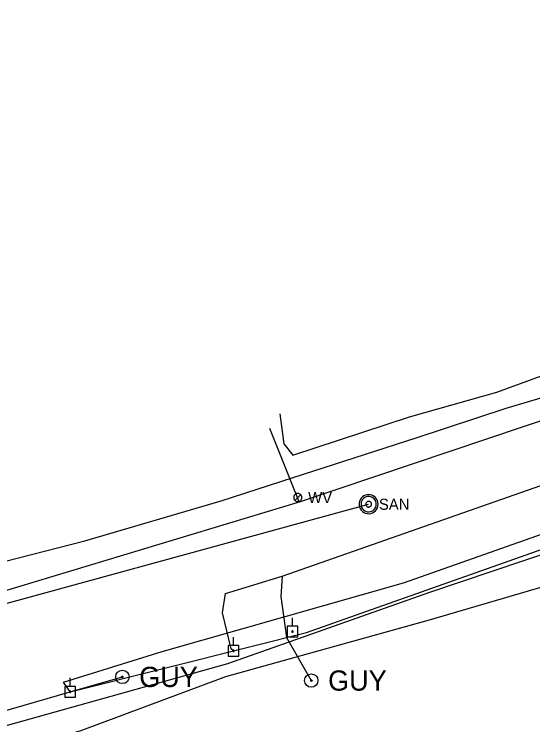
# Model space of a CAD drawing. Extents: x 596028 to 606371, y 330010 to 403088.
# Drawn here: x 604579.4 to 604758.9, y 333688.9 to 333935 of the extents above; entities that cross this region are included whole.
import ezdxf

# ---------------------------------------------------------------- set-up
doc = ezdxf.new("R2010")
doc.units = 0
for name, color, linetype in [('E_UTL_E_UG', 7, 'Continuous'), ('E_UTL_EGuyWire', 7, 'Continuous'), ('E_UTL_EPowerPole', 7, 'Continuous'), ('E_UTL_FO_UG_QWEST', 7, 'Continuous'), ('E_UTL_G_UG', 7, 'Continuous'), ('E_UTL_Overhead', 7, 'Continuous'), ('E_UTL_SAN_MH', 7, 'Continuous'), ('E_UTL_SAN_UG', 7, 'Continuous'), ('E_UTL_T_UG', 7, 'Continuous'), ('E_UTL_W', 7, 'Continuous'), ('E_UTL_W_UG', 7, 'Continuous')]:
    doc.layers.add(name, color=color, linetype=linetype)

msp = doc.modelspace()

# ---------------------------------------------------------------- linework, layer by layer
at = {"layer": 'E_UTL_E_UG'}
msp.add_line((604671.71, 333733.36), (604673.7, 333719.09), dxfattribs=at)
for points in [[(604440.14, 333718.83), (604480.42, 333725.03), (604538.85, 333736.02), (604603.87, 333752.62), (604651.09, 333766.43), (604675.97, 333774.58), (604718.55, 333788.33), (604749.73, 333798.5), (604768.73, 333804.21), (604803.48, 333815.07), (604806.49, 333819.63), (604807.09, 333825.4), (604807.44, 333834.72)], [(604598.8, 333700.36), (604596.5, 333703.7), (604630.64, 333714.29), (604714.18, 333738.06), (604794.04, 333766.23), (604819.54, 333774.15), (604828.3, 333774.47), (604835.57, 333767), (604842.31, 333740.21), (604846.52, 333720.82)], [(604655.31, 333714.51), (604654.49, 333715.25), (604651.55, 333727.64), (604652.56, 333734.31), (604672.23, 333740.35), (604765.98, 333773.32)], [(604672.23, 333740.35), (604671.71, 333733.36)]]:
    msp.add_lwpolyline(points, dxfattribs=at)
at = {"layer": 'E_UTL_EGuyWire'}
for p, q in [((604673.7, 333719.09), (604682.25, 333704.22)), ((604598.8, 333700.36), (604616.86, 333705.48))]:
    msp.add_line(p, q, dxfattribs=at)
for centre, radius in [((604616.86, 333705.48), 2.33), ((604682.25, 333704.22), 2.33), ((604616.86, 333705.48), 0.292), ((604682.25, 333704.22), 0.292)]:
    msp.add_circle(centre, radius, dxfattribs=at)
at = {"layer": 'E_UTL_EPowerPole'}
for points in [[(604675.7, 333723.02), (604675.7, 333725.93)], [(604677.55, 333723.02), (604673.86, 333723.02)], [(604673.86, 333723.02), (604673.86, 333719.33)], [(604675.97, 333721.18), (604675.97, 333721.22), (604675.96, 333721.27), (604675.94, 333721.31), (604675.91, 333721.34), (604675.87, 333721.37), (604675.83, 333721.39), (604675.79, 333721.41), (604675.75, 333721.42), (604675.7, 333721.41), (604675.66, 333721.4), (604675.62, 333721.38), (604675.58, 333721.36), (604675.55, 333721.32), (604675.52, 333721.29), (604675.51, 333721.24), (604675.5, 333721.2), (604675.5, 333721.15), (604675.51, 333721.11), (604675.52, 333721.07), (604675.55, 333721.03), (604675.58, 333721), (604675.62, 333720.97), (604675.66, 333720.95), (604675.7, 333720.94), (604675.75, 333720.94), (604675.79, 333720.95), (604675.83, 333720.96), (604675.87, 333720.98), (604675.91, 333721.01), (604675.94, 333721.05), (604675.96, 333721.09), (604675.97, 333721.13), (604675.97, 333721.18)], [(604677.55, 333719.33), (604677.55, 333723.02)], [(604655.28, 333716.36), (604655.28, 333719.26)], [(604673.86, 333719.33), (604677.55, 333719.33)], [(604657.13, 333716.36), (604653.44, 333716.36)], [(604653.44, 333716.36), (604653.44, 333712.66)], [(604657.13, 333712.66), (604657.13, 333716.36)], [(604655.55, 333714.51), (604655.55, 333714.56), (604655.54, 333714.6), (604655.51, 333714.64), (604655.49, 333714.68), (604655.45, 333714.71), (604655.41, 333714.73), (604655.37, 333714.74), (604655.33, 333714.75), (604655.28, 333714.75), (604655.24, 333714.74), (604655.19, 333714.72), (604655.16, 333714.69), (604655.13, 333714.66), (604655.1, 333714.62), (604655.09, 333714.58), (604655.08, 333714.54), (604655.08, 333714.49), (604655.09, 333714.45), (604655.1, 333714.4), (604655.13, 333714.37), (604655.16, 333714.33), (604655.19, 333714.31), (604655.24, 333714.29), (604655.28, 333714.28), (604655.33, 333714.27), (604655.37, 333714.28), (604655.41, 333714.3), (604655.45, 333714.32), (604655.49, 333714.35), (604655.51, 333714.38), (604655.54, 333714.42), (604655.55, 333714.47), (604655.55, 333714.51)], [(604653.44, 333712.66), (604657.13, 333712.66)], [(604598.77, 333702.21), (604598.77, 333705.12)], [(604600.61, 333702.21), (604596.92, 333702.21)], [(604596.92, 333702.21), (604596.92, 333698.52)], [(604600.61, 333698.52), (604600.61, 333702.21)], [(604599.04, 333700.36), (604599.03, 333700.41), (604599.02, 333700.45), (604599, 333700.49), (604598.97, 333700.53), (604598.94, 333700.56), (604598.9, 333700.58), (604598.86, 333700.6), (604598.81, 333700.6), (604598.77, 333700.6), (604598.72, 333700.59), (604598.68, 333700.57), (604598.64, 333700.54), (604598.61, 333700.51), (604598.59, 333700.47), (604598.57, 333700.43), (604598.56, 333700.39), (604598.56, 333700.34), (604598.57, 333700.3), (604598.59, 333700.25), (604598.61, 333700.22), (604598.64, 333700.18), (604598.68, 333700.16), (604598.72, 333700.14), (604598.77, 333700.13), (604598.81, 333700.13), (604598.86, 333700.13), (604598.9, 333700.15), (604598.94, 333700.17), (604598.97, 333700.2), (604599, 333700.24), (604599.02, 333700.28), (604599.03, 333700.32), (604599.04, 333700.36)], [(604596.92, 333698.52), (604600.61, 333698.52)]]:
    msp.add_lwpolyline(points, dxfattribs=at)
at = {"layer": 'E_UTL_FO_UG_QWEST'}
msp.add_lwpolyline([(604064.36, 333597.95), (604125.52, 333607.24), (604222.69, 333622.89), (604294.58, 333635.82), (604348.76, 333642.01), (604429.81, 333649.86), (604519.71, 333664), (604602.19, 333686.85), (604652.71, 333705.68), (604723.21, 333725.29), (604801.25, 333748.09), (604835.09, 333762.42), (604848.03, 333769.94), (604883.85, 333785.99), (604890.17, 333789.47), (604890.94, 333790.11), (604892.16, 333796.08), (604892.06, 333804.65), (604893.55, 333818.96), (604893.11, 333877.27), (604889.73, 333952.96), (604886.58, 334030.08), (604884.67, 334105.68), (604880.28, 334183.13)], dxfattribs=at)
at = {"layer": 'E_UTL_G_UG'}
for points in [[(604716.26, 333795.51), (604746.45, 333804.07), (604803.5, 333825.03), (604821.12, 333830.43), (604832.44, 333836.15), (604844.53, 333839.78), (604848.34, 333839.76)], [(604671.41, 333796.64), (604672.81, 333786.15), (604675.87, 333782.29), (604716.26, 333795.51)]]:
    msp.add_lwpolyline(points, dxfattribs=at)
at = {"layer": 'E_UTL_Overhead'}
msp.add_lwpolyline([(604271.13, 333669.29), (604434.72, 333660.07), (604570.4, 333692.06), (604598.8, 333700.36), (604662.24, 333716.27), (604680.63, 333720.84), (604769.68, 333752.42)], dxfattribs=at)
at = {"layer": 'E_UTL_SAN_MH'}
for points in [[(604705.4, 333765.29), (604705.34, 333765.92), (604705.17, 333766.52), (604704.88, 333767.08), (604704.49, 333767.57), (604704.02, 333767.98), (604703.47, 333768.29), (604702.88, 333768.5), (604702.26, 333768.59), (604701.63, 333768.56), (604701.02, 333768.41), (604700.45, 333768.15), (604699.94, 333767.79), (604699.51, 333767.33), (604699.17, 333766.8), (604698.94, 333766.22), (604698.82, 333765.61), (604698.82, 333764.98), (604698.94, 333764.36), (604699.17, 333763.78), (604699.51, 333763.25), (604699.94, 333762.8), (604700.45, 333762.43), (604701.02, 333762.17), (604701.63, 333762.03), (604702.26, 333762), (604702.88, 333762.09), (604703.47, 333762.29), (604704.02, 333762.6), (604704.49, 333763.02), (604704.88, 333763.51), (604705.17, 333764.07), (604705.34, 333764.67), (604705.4, 333765.29)], [(604704.74, 333765.29), (604704.7, 333765.79), (604704.55, 333766.27), (604704.32, 333766.72), (604704.01, 333767.11), (604703.63, 333767.44), (604703.2, 333767.69), (604702.73, 333767.86), (604702.23, 333767.93), (604701.73, 333767.91), (604701.24, 333767.79), (604700.78, 333767.58), (604700.37, 333767.29), (604700.03, 333766.92), (604699.76, 333766.5), (604699.57, 333766.04), (604699.48, 333765.54), (604699.48, 333765.04), (604699.57, 333764.55), (604699.76, 333764.08), (604700.03, 333763.66), (604700.37, 333763.3), (604700.78, 333763.01), (604701.24, 333762.8), (604701.73, 333762.68), (604702.23, 333762.66), (604702.73, 333762.73), (604703.2, 333762.89), (604703.63, 333763.14), (604704.01, 333763.47), (604704.32, 333763.87), (604704.55, 333764.31), (604704.7, 333764.79), (604704.74, 333765.29)], [(604703.09, 333765.29), (604703.08, 333765.48), (604703.02, 333765.66), (604702.94, 333765.83), (604702.82, 333765.98), (604702.68, 333766.1), (604702.51, 333766.19), (604702.34, 333766.25), (604702.15, 333766.28), (604701.96, 333766.27), (604701.78, 333766.23), (604701.61, 333766.15), (604701.45, 333766.04), (604701.33, 333765.9), (604701.22, 333765.75), (604701.15, 333765.57), (604701.12, 333765.39), (604701.12, 333765.2), (604701.15, 333765.01), (604701.22, 333764.84), (604701.33, 333764.68), (604701.45, 333764.54), (604701.61, 333764.44), (604701.78, 333764.36), (604701.96, 333764.31), (604702.15, 333764.3), (604702.34, 333764.33), (604702.51, 333764.39), (604702.68, 333764.49), (604702.82, 333764.61), (604702.94, 333764.76), (604703.02, 333764.92), (604703.08, 333765.11), (604703.09, 333765.29)]]:
    msp.add_lwpolyline(points, dxfattribs=at)
at = {"layer": 'E_UTL_SAN_UG'}
msp.add_line((604508.31, 333712.16), (604702.1, 333765.29), dxfattribs=at)
at = {"layer": 'E_UTL_T_UG'}
msp.add_lwpolyline([(604287.56, 333667.46), (604321.18, 333666.93), (604440.94, 333666.46), (604493.47, 333670.08), (604529.7, 333676.11), (604555.97, 333682.92), (604653.39, 333710.18), (604723.28, 333734.82), (604777.43, 333753.12), (604798.61, 333759.72), (604824.33, 333769.22), (604827.36, 333771.7), (604818.65, 333799.13), (604813.51, 333815.63), (604833.03, 333823.91), (604843.16, 333830.13), (604845.76, 333834.11), (604845.18, 333862.78), (604844.73, 333915.07), (604844.08, 333962.32)], dxfattribs=at)
at = {"layer": 'E_UTL_W'}
for points in [[(604679.02, 333767.61), (604679, 333767.88), (604678.92, 333768.14), (604678.8, 333768.38), (604678.63, 333768.59), (604678.42, 333768.77), (604678.19, 333768.91), (604677.93, 333768.99), (604677.66, 333769.03), (604677.39, 333769.02), (604677.13, 333768.96), (604676.88, 333768.84), (604676.66, 333768.69), (604676.48, 333768.49), (604676.33, 333768.26), (604676.23, 333768.01), (604676.18, 333767.74), (604676.18, 333767.47), (604676.23, 333767.21), (604676.33, 333766.96), (604676.48, 333766.73), (604676.66, 333766.53), (604676.88, 333766.37), (604677.13, 333766.26), (604677.39, 333766.2), (604677.66, 333766.18), (604677.93, 333766.22), (604678.19, 333766.31), (604678.42, 333766.45), (604678.63, 333766.62), (604678.8, 333766.84), (604678.92, 333767.08), (604679, 333767.34), (604679.02, 333767.61)], [(604676.59, 333766.6), (604678.6, 333768.62)]]:
    msp.add_lwpolyline(points, dxfattribs=at)
at = {"layer": 'E_UTL_W_UG'}
msp.add_line((604678.06, 333766.11), (604667.86, 333791.5), dxfattribs=at)
msp.add_lwpolyline([(604515.23, 333705.55), (604537.69, 333723.74), (604678.54, 333766.26), (604808.21, 333809.92), (604813.3, 333825.61), (604848.02, 333839.34), (604848.13, 333846.41)], dxfattribs=at)

# ---------------------------------------------------------------- texts
at = {"layer": 'E_UTL_EGuyWire'}
for p in [(604622.69, 333701.98), (604688.08, 333700.72)]:
    msp.add_text('GUY', height=7, dxfattribs=at).set_placement(p)
at = {"layer": 'E_UTL_SAN_MH'}
msp.add_text('SAN', height=3.849, dxfattribs=at).set_placement((604705.67, 333763.35))
at = {"layer": 'E_UTL_W'}
msp.add_text('WV', height=3.85, dxfattribs=at).set_placement((604681.16, 333765.68))

doc.saveas('drawing.dxf')
